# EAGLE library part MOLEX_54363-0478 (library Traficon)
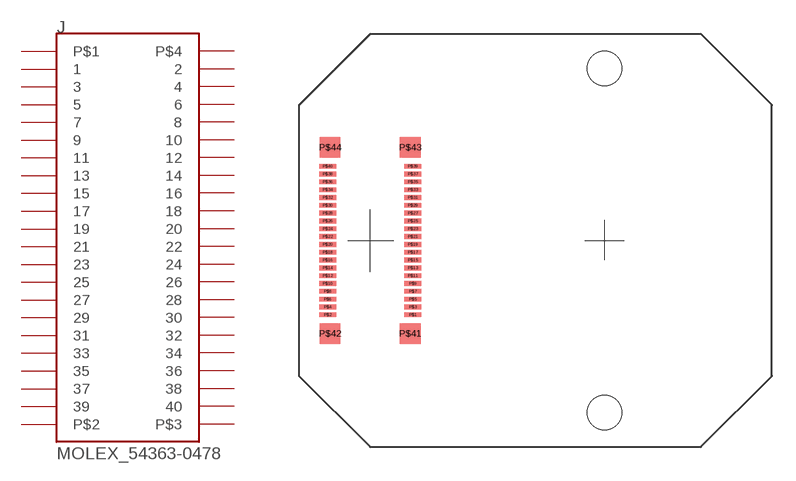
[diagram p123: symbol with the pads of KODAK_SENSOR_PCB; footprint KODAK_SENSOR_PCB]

Designator prefix J

## MOLEX_54363-0478  [KODAK_SENSOR_PCB]
P$1  1
P$2  2
P$3  3
P$4  4
P$5  5
P$6  6
P$7  7
P$8  8
P$9  9
P$10  10
P$11  11
P$12  12
P$13  13
P$14  14
P$15  15
P$16  16
P$17  17
P$18  18
P$19  19
P$20  20
P$21  21
P$22  22
P$23  23
P$24  24
P$25  25
P$26  26
P$27  27
P$28  28
P$29  29
P$30  30
P$31  31
P$32  32
P$33  33
P$34  34
P$35  35
P$36  36
P$37  37
P$38  38
P$39  39
P$40  40
P$41  P$1
P$42  P$2
P$43  P$3
P$44  P$4

## Footprint KODAK_SENSOR_PCB (pad centres in mm)
smd 1.1 x 0.3: P$1 -7.836,-4.753; P$2 -13.276,-4.753; P$3 -7.836,-4.253; P$4 -13.276,-4.253; P$5 -7.836,-3.753; P$6 -13.276,-3.753; P$7 -7.836,-3.253; P$8 -13.276,-3.253; P$9 -7.836,-2.753; P$10 -13.276,-2.753; P$11 -7.836,-2.253; P$12 -13.276,-2.253; P$13 -7.836,-1.753; P$14 -13.276,-1.753; P$15 -7.836,-1.253; P$16 -13.276,-1.253; P$17 -7.836,-0.753; P$18 -13.276,-0.753; P$19 -7.836,-0.253; P$20 -13.276,-0.253; P$21 -7.836,0.247; P$22 -13.276,0.247; P$23 -7.836,0.747; P$24 -13.276,0.747; P$25 -7.836,1.247; P$26 -13.276,1.247; P$27 -7.836,1.747; P$28 -13.276,1.747; P$29 -7.836,2.247; P$30 -13.276,2.247; P$31 -7.836,2.747; P$32 -13.276,2.747; P$33 -7.836,3.247; P$34 -13.276,3.247; P$35 -7.836,3.747; P$36 -13.276,3.747; P$37 -7.836,4.247; P$38 -13.276,4.247; P$39 -7.836,4.747; P$40 -13.276,4.747
smd 1.32 x 1.3: P$41 -7.996,-5.953; P$42 -13.116,-5.953; P$43 -7.996,5.947; P$44 -13.116,5.947
hole 2.2 at 4.4,11
hole 2.2 at 4.4,-11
